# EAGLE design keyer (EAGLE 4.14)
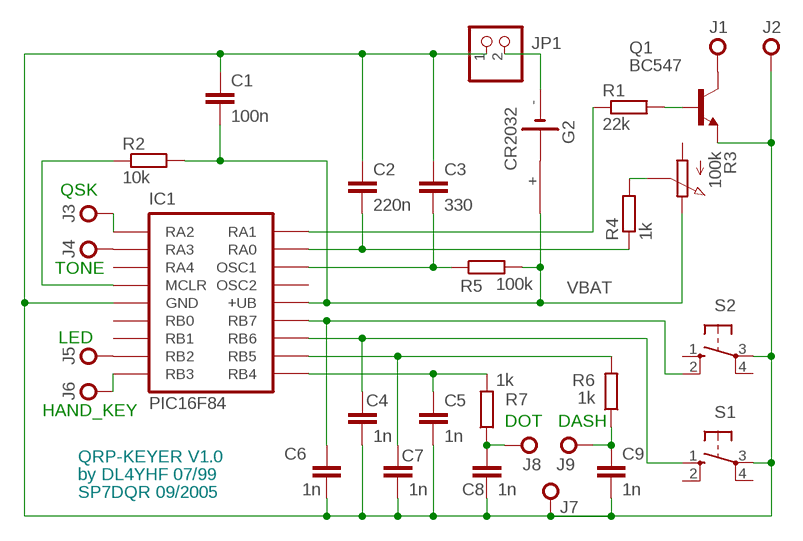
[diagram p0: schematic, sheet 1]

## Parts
C1  100n  SMD_C1206B  [R1206B]
C2  220n  C-EU075-032X103  [C075-032X103]
C3  330  C-EU050-024X044  [C050-024X044]
C4  1n  C-EU050-024X044  [C050-024X044]
C5  1n  C-EU050-024X044  [C050-024X044]
C6  1n  C-EU050-024X044  [C050-024X044]
C7  1n  C-EU050-024X044  [C050-024X044]
C8  1n  C-EU050-024X044  [C050-024X044]
C9  1n  C-EU050-024X044  [C050-024X044]
G2  CR2032  B2430UNI  [B2430UNI]
IC1  16F84P  [DIL18]
J1  PUNKT  [PUNKT_LUTOWNICZY]
J2  PUNKT  [PUNKT_LUTOWNICZY]
J3  QSK  PUNKT  [PUNKT_LUTOWNICZY]
J4  TONE  PUNKT  [PUNKT_LUTOWNICZY]
J5  LED  PUNKT  [PUNKT_LUTOWNICZY]
J6  HAND-KEY  PUNKT  [PUNKT_LUTOWNICZY]
J7  PUNKT  [PUNKT_LUTOWNICZY]
J8  PUNKT  [PUNKT_LUTOWNICZY]
J9  PUNKT  [PUNKT_LUTOWNICZY]
JP1  PINHD-1X2  [1X02]
Q1  BC547  NPN  [TO-92_SZER]
R1  22k  R-EU_0204/7  [0204/7]
R2  10k  R-EU_0204/7  [0204/7]
R3  100k  POTCIP160C  [CIP160C]
R4  1k  R-EU_0204/7  [0204/7]
R5  100k  R-EU_0204/7  [0204/7]
R6  1k  R-EU_0204/7  [0204/7]
R7  1k  R-EU_0204/7  [0204/7]
S1  40-XX  [B3F-40XX]
S2  40-XX  [B3F-40XX]

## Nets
GND: C1.1 C2.1 C3.1 C4.2 C5.2 C6.2 C7.2 C8.2 C9.2 IC1.5(GND) J2.MP J7.MP JP1.1 Q1.E S1.3(P) S2.3(P)
N$1: IC1.18(RA1) R1.1
N$2: C2.2 IC1.17(RA0) R4.1
N$3: C3.2 IC1.16(OSC1) R5.1
N$4: R3.P$2 R4.2
N$5: C7.1 IC1.11(RB5) R6.2
N$6: C5.1 IC1.10(RB4) R7.2
N$7: C6.1 IC1.13(RB7) S2.2(S1)
N$8: C4.1 IC1.12(RB6) S1.1(S)
N$9: C8.1 J8.MP R7.1
N$10: IC1.4(MCLR) R2.1
N$11: C9.1 J9.MP R6.1
N$12: Q1.B R1.2
N$13: J1.MP Q1.C
N$14: IC1.2(RA3) J4.MP
N$15: IC1.9(RB3) J6.MP
N$16: IC1.1(RA2) J3.MP
N$17: IC1.8(RB2) J5.MP
N$18: G2.- JP1.2
VBAT: C1.2 G2.+ IC1.14(+UB) R2.2 R3.P$3 R5.2
Unconnected: G2.+@1(+) G2.+@2(+) G2.+@3(+) G2.+@4(+) G2.-@1(-) IC1.3(RA4) IC1.6(RB0) IC1.7(RB1) IC1.15(OSC2) R3.P$1 S1.2(S1) S1.4(P1) S2.1(S) S2.4(P1)

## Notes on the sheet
- QSK
- TONE
- LED
- HAND_KEY
- DOT | DASH
- QRP-KEYER V1.0
- by DL4YHF 07/99
- SP7DQR 09/2005

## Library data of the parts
C1 = _SP7DQR:SMD_C1206B
C2-C9 = rcl:C-EU: CAPACITOR, European symbol
G2 = battery:B2430UNI: LI BATTERY
IC1 = yhf_spec:16F84P
J1-J9 = _SP7DQR:PUNKT
JP1 = pinhead:PINHD-1X2: PIN HEADER
Q1 = _SP7DQR:NPN
R1 R2 R4-R7 = rcl:R-EU_: RESISTOR, European symbol
R3 = _SP7DQR:POTCIP160C
S1 S2 = switch-omron:40-XX: OMRON SWITCH

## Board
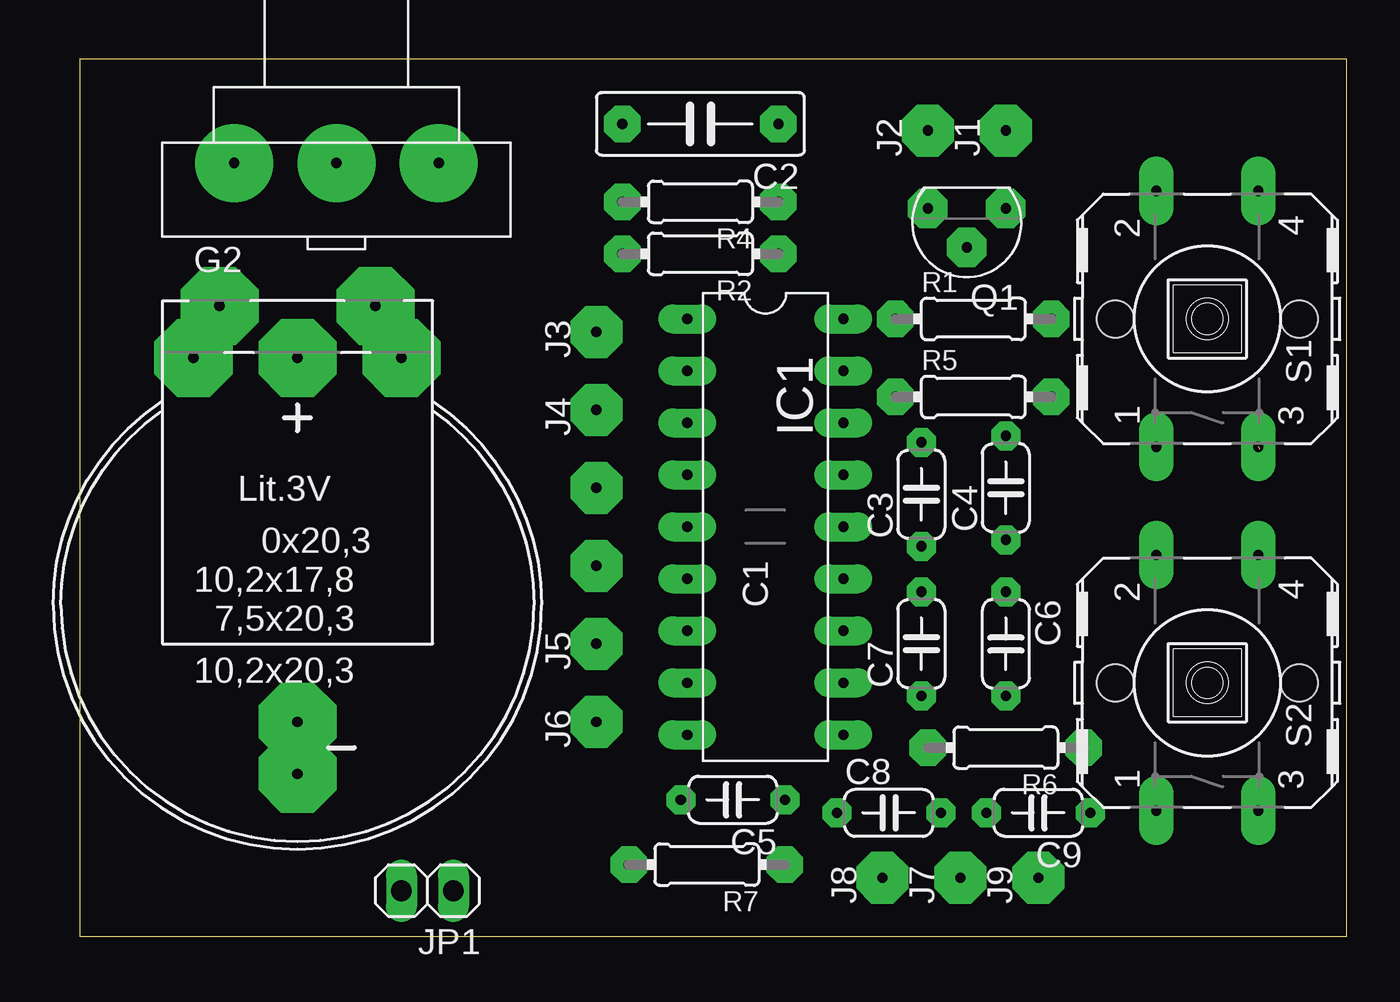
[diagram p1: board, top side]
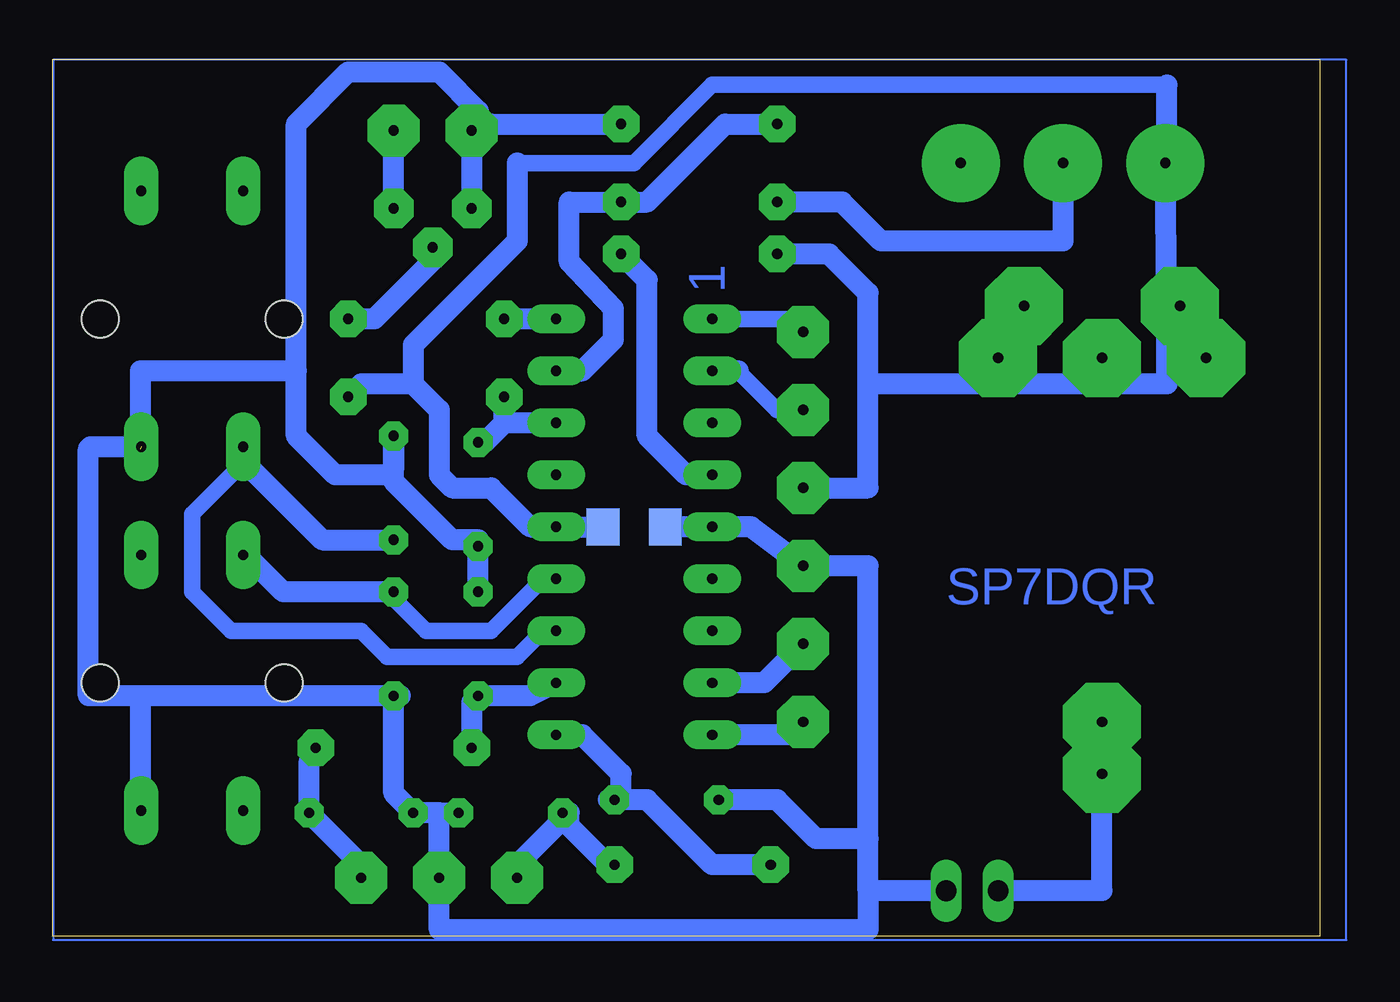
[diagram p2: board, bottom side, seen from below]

Size 61.9 x 42.85 mm. Coordinates in mm from the lower left corner, seen from the top.
Outline: 0,0 61.9,0 61.9,42.85 0,42.85 0,0
Copper layers 16: Bottom 0.035mm
Design rules "default": minimum track width 10mil, minimum drill 24mil, track to track 8mil, track to pad 8mil, pad to pad 8mil, via to via 8mil, smd to smd 8mil, copper to edge 0mil, drill to drill 8mil, minimum pad ring 10mil, minimum via ring 8mil, stop-mask expansion 4mil, vias tented up to drill 0mil, thermal gap 10mil

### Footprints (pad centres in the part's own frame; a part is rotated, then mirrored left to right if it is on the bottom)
R1206B = smd 1.6 x 1.803 bottom: 1 -1.524,0; 2 1.524,0
C075-032X103 = drill 0.5 pad 1.778 octagon: 1 -3.81,0; 2 3.81,0
C050-024X044 = drill 0.5 pad 1.422 octagon: 1 -2.54,0; 2 2.54,0
B2430UNI = drill 0.5 pad 3.81 octagon: + 3.81,14.605; +@1 -3.81,14.605; +@2 -5.08,12.065; +@3 5.08,12.065; +@4 0,12.065; - 0,-5.715; -@1 0,-8.255
DIL18 = drill 0.5 pad 1.422 long: 1 -10.16,-3.81; 2 -7.62,-3.81; 3 -5.08,-3.81; 4 -2.54,-3.81; 5 0,-3.81; 6 2.54,-3.81; 7 5.08,-3.81; 8 7.62,-3.81; 9 10.16,-3.81; 10 10.16,3.81; 11 7.62,3.81; 12 5.08,3.81; 13 2.54,3.81; 14 0,3.81; 15 -2.54,3.81; 16 -5.08,3.81; 17 -7.62,3.81; 18 -10.16,3.81
PUNKT_LUTOWNICZY = drill 0.5 pad 2.54 octagon: MP 0,0
1X02 = drill 1.016 long: 1 -1.27,0; 2 1.27,0
TO-92_SZER = drill 0.5 pad 1.93 octagon: B 0,1.27; C -1.905,-0.635; E 1.905,-0.635
0204/7 = drill 0.5 pad 1.778 octagon: 1 -3.81,0; 2 3.81,0
CIP160C = drill 0.5 pad 3.81 round: P$1 0,-5; P$2 0,0; P$3 0,5
B3F-40XX = drill 0.5 pad 1.676 long: 1 -6.248,2.489; 2 6.248,2.489; 3 -6.248,-2.489; 4 6.248,-2.489 | hole 1.803: 0,-4.496; 0,4.496

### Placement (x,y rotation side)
C1  33.49,20 0 top
C2  30.31,39.68 180 top
C3  41.11,21.59 90 top
C4  45.24,21.9 90 top
C5  31.9,6.66 180 top
C6  45.24,14.28 270 top
C7  41.11,14.28 90 top
C8  39.52,6.03 0 top
C9  46.82,6.03 180 top
G2  10.63,16.19 0 top
IC1  33.49,20 270 top
J1  45.24,39.37 90 top
J2  41.43,39.37 90 top
J3  25.23,29.52 90 top
J4  25.23,25.71 90 top
J5  25.23,14.28 90 top
J6  25.23,10.47 90 top
J7  43.02,2.85 90 top
J8  39.2,2.85 90 top
J9  46.82,2.85 90 top
JP1  16.98,2.22 180 top
Q1  43.33,34.92 180 top
R1  43.65,30.16 0 top
R2  30.31,33.33 180 top
R3  12.54,37.78 90 top
R4  30.31,35.87 180 top
R5  43.65,26.35 0 top
R6  45.24,9.2 180 top
R7  30.63,3.49 180 top
S1  55.08,30.16 90 top
S2  55.08,12.38 90 top

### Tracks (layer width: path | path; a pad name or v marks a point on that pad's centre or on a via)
GND  (1 unrouted)
  Bottom 1.016: 43.02,6.03 C8.2 | 43.02,6.03 C9.2 45.24,6.98 C6.2 | 43.02,6.03 J7.MP 43.02,0.31 22.06,0.31 22.06,2.22 | C6.2 44.92,11.74 | C2.1 40.48,39.68 41.11,39.05 41.43,39.68 J2.MP | Q1.E 41.43,35.87 41.11,35.24 Q1.E | J2.MP Q1.E | C5.2 26.5,6.66 24.6,4.76 22.06,4.76 | C7.2 C3.1 41.11,19.36 42.38,19.36 45.24,22.22 C4.2 45.24,22.86 45.55,22.54 48.09,22.54 50,24.44 50,27.62 | J2.MP 41.11,39.68 41.11,40.32 43.02,42.22 47.46,42.22 50,39.68 50,27.62 | 22.06,2.22 22.06,4.76 | 22.06,4.76 22.06,18.09 25.23,18.09 27.77,20 IC1.5 C1.1 | JP1.1 22.06,2.22 | C6.2 57.62,11.74 | S2.3 57.57,6.08 57.62,6.03 57.62,11.74 | S1.3 60.06,23.91 60.16,23.81 60.16,11.74 57.62,11.74 | 57.62,23.81 57.62,27.62 50,27.62
N$1
  Bottom 1.016: IC1.18 R1.1
N$2
  Bottom 1.016: IC1.17 36.03,27.62 34.51,29.14 34.51,30.67 36.66,32.95 36.66,35.87 R4.1 32.85,35.87 29.04,39.68 C2.2
N$3
  Bottom 1.016: IC1.16 39.84,25.08 | 39.84,25.08 R5.1 | C3.2 40.79,24.12 39.84,25.08
N$4
  Bottom 1.016: R3.P$2 12.54,33.97 21.42,33.97 23.33,35.87 R4.2
N$5
  Bottom 1.016: R6.2 41.43,11.43 C7.1 38.57,11.74 IC1.11 36.66,12.38
N$6
  Bottom 1.016: IC1.10 36.03,9.84 34.12,7.93 34.12,6.66 | R7.2 29.68,3.49 32.85,6.66 34.12,6.66 | 34.12,6.66 C5.1 34.76,6.66
N$7
  Bottom 0.813: 37.94,17.46 40.48,14.92 43.65,14.92 45.55,16.82
  Bottom 1.016: IC1.13 37.94,17.46 | 45.55,16.82 C6.1 50.63,16.82 52.54,18.73 52.59,18.68 S2.2
N$8
  Bottom 0.813: 37.94,14.92 39.2,13.65 45.55,13.65 46.82,14.92 53.17,14.92 55.08,16.82 55.08,20.63 52.54,23.17
  Bottom 1.016: IC1.12 37.94,14.92 | C4.1 48.73,19.36 52.54,23.17 52.59,23.22 S1.1
N$9
  Bottom 1.016: R7.1 34.76,3.49 36.66,5.39 36.66,6.03 | 36.66,6.03 C8.1 | J8.MP 39.2,3.49 36.66,6.03
N$10
  Bottom 1.016: R2.1 32.85,32.06 32.85,24.44 30.95,22.54 IC1.4
N$11
  Bottom 1.016: J9.MP 46.82,3.49 C9.1 49.37,8.57 48.73,9.2 R6.1
N$12
  Bottom 1.016: Q1.B 43.33,33.02 46.19,30.16 R1.2
N$13
  Bottom 1.016: Q1.C 45.24,35.87 45.55,35.24 Q1.C | Q1.C J1.MP
N$14
  Bottom 0.813: 28.41,27.62 26.5,25.71 J4.MP
  Bottom 1.016: 28.41,27.62 IC1.2
N$15
  Bottom 1.016: J6.MP 25.87,9.84 IC1.9
N$16
  Bottom 0.813: IC1.1 25.87,30.16 J3.MP
N$17
  Bottom 1.016: J5.MP 27.14,12.38 IC1.8
N$18
  Bottom 1.016: JP1.2 10.63,2.22 G2.-
N$19
  Bottom 0.1: -1.3,42.81 61.87,42.81 61.87,-0.19 -1.3,-0.19 -1.3,42.81
N$22  (via drill 0.5 pad 2.54)
  Bottom 1.016: v25.23,21.9 22.06,21.9 22.06,26.98
N$23  (via drill 0.5 pad 2.54)
  other vias: 25.23,18.09
VBAT
  Bottom 0.813: 39.2,37.78 33.49,37.78 29.68,41.59 7.46,41.59
  Bottom 1.016: 44.28,26.98 43.02,25.71 43.02,22.54 42.38,21.9 40.48,21.9 38.57,20 IC1.14 C1.2 34.76,20 | 44.28,26.98 46.82,26.98 R5.2 | 39.2,37.78 39.2,33.97 44.28,28.89 44.28,26.98 | 7.46,41.59 7.46,37.78 7.54,37.7 R3.P$3 7.46,30.79 7.46,26.98 14.44,26.98 | R2.2 23.96,33.33 22.06,31.43 22.06,26.98 14.44,26.98 | 14.44,26.98 G2.+

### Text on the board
Bottom: 1 | SP7DQR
